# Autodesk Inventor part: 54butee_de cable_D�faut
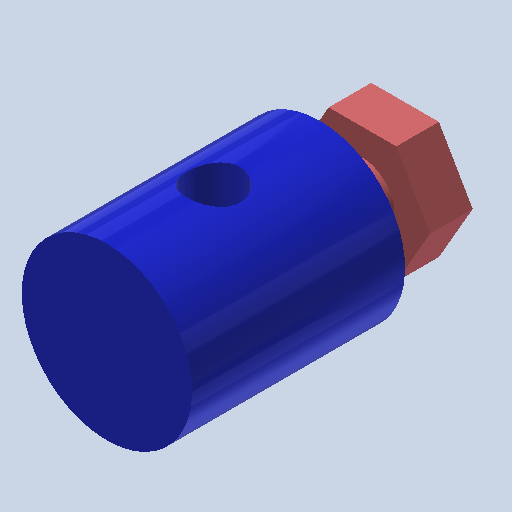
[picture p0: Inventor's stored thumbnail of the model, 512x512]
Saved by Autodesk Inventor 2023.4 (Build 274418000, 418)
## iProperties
Created: 2011-01
Part Number: 54butee_de cable_D�faut
Document SubType Name: Modeling
Designer: eric
Density: 1 g/cm^3
Mass: 0.530405 g
Surface Area: 4.98383 cm^2
Volume: 0.530405 cm^3
Material: Générique
Appearance: 255,128,128
Author: eric
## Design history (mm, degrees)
feature "Base1"
node "Corps solides"
node "Corps surfaciques"
node "Solide1"
